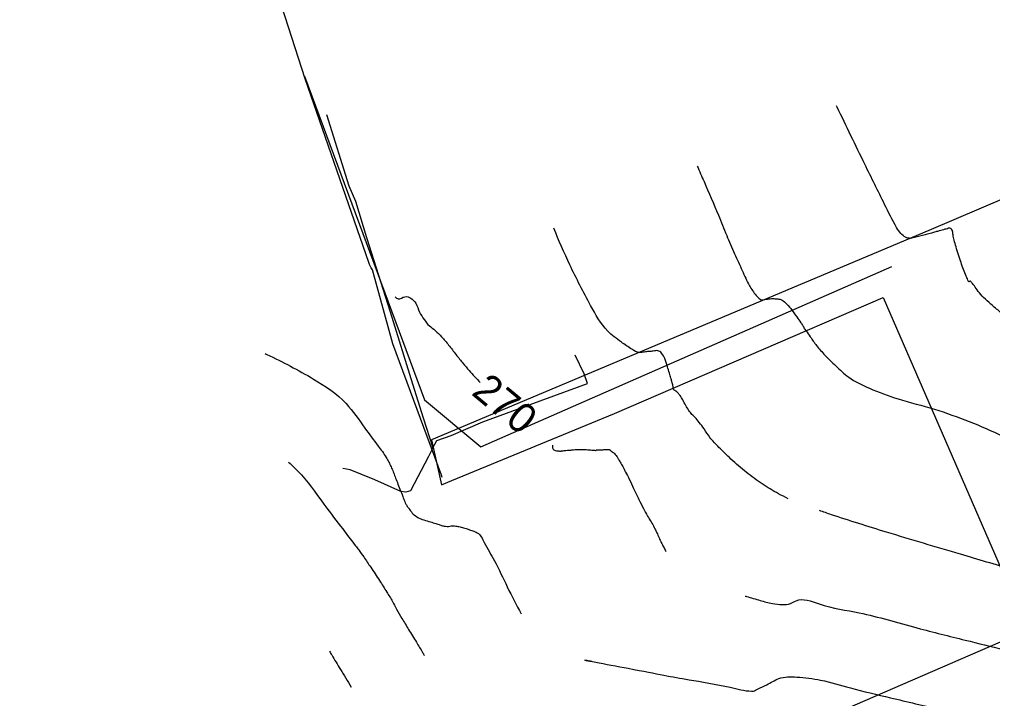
# Model space of a CAD drawing. Extents: x -478232 to -472707, y -1118753 to -1113967.
# Drawn here: x -475821.3 to -475689.5, y -1117014.2 to -1116922.3 of the extents above; entities that cross this region are included whole.
import ezdxf

# ---------------------------------------------------------------- set-up
doc = ezdxf.new("R2010")
doc.units = 0
for name, color, linetype in [('ObPÚ', 7, 'Continuous'), ('telekomunikační kabel_O2', 7, 'Continuous'), ('VAK_vodovod', 7, 'Continuous'), ('Vrstevnice_hlavni', 7, 'Continuous'), ('Vrstevnice_popis', 7, 'Continuous'), ('Vrstevnice_vedlejsi', 7, 'Continuous')]:
    doc.layers.add(name, color=color, linetype=linetype)

msp = doc.modelspace()

# ---------------------------------------------------------------- linework, layer by layer
at = {"layer": 'ObPÚ'}
msp.add_lwpolyline([(-475634.09, -1116923.52), (-475698.19, -1116950.87), (-475765.52, -1116979.2), (-475764.15, -1116985.27), (-475762.77, -1116984.68), (-475740.75, -1116975.6), (-475704.37, -1116959.91), (-475684.75, -1117004.96), (-475721.12, -1117020.7), (-475752.88, -1117034.21), (-475749.21, -1117050.03), (-475744.47, -1117062.49), (-475748.91, -1117064.2), (-475744.85, -1117076.56), (-475754.59, -1117081.64), (-475740.69, -1117110.42), (-475761.49, -1117122.43), (-475769.31, -1117126.94), (-475775.61, -1117130.12), (-475776.93, -1117131.38), (-475801.94, -1117143.82), (-475807.07, -1117146.05), (-475816.15, -1117150.33), (-475821.3, -1117143.22)], dxfattribs=at)
at = {"layer": 'telekomunikační kabel_O2'}
for points in [[(-475779.72, -1116935.16), (-475776.72, -1116944.8), (-475775.82, -1116946.89)], [(-475775.82, -1116946.89), (-475774.3, -1116951.81), (-475771.12, -1116961.84), (-475768.06, -1116971.62), (-475766.62, -1116976.22), (-475765.34, -1116980.29)], [(-475765.34, -1116980.29), (-475764.8, -1116979.28), (-475762.86, -1116978.62), (-475758.55, -1116976.73), (-475744.37, -1116971.54), (-475744.83, -1116970.26), (-475746.06, -1116967.73)], [(-475765.34, -1116980.29), (-475765.92, -1116981.46), (-475768.35, -1116986.07), (-475768.98, -1116986.28), (-475769.68, -1116986.19), (-475773.18, -1116984.59), (-475776.5, -1116983.23), (-475777.53, -1116983.05)]]:
    msp.add_lwpolyline(points, dxfattribs=at)
at = {"layer": 'VAK_vodovod'}
for points in [[(-475764.07, -1116984.29), (-475764.159, -1116983.95), (-475770.76, -1116966.2), (-475773.519, -1116956.18), (-475773.699, -1116955.909), (-475773.909, -1116955.44), (-475773.98, -1116955.18), (-475782.599, -1116930.34), (-475789.389, -1116909.29), (-475792.36, -1116901.129), (-475795.449, -1116892.25), (-475795.679, -1116891.569), (-475801.449, -1116877.079), (-475803.873, -1116870.356), (-475810.739, -1116851.899), (-475813.889, -1116838.01), (-475814.349, -1116835.61), (-475816.44, -1116816.799), (-475816.731, -1116810.878)], [(-475782.684, -1116929.977), (-475766.44, -1116973.781), (-475758.82, -1116980.133), (-475703.189, -1116955.74)]]:
    msp.add_lwpolyline(points, dxfattribs=at)
at = {"layer": 'Vrstevnice_hlavni'}
for points in [[(-475770.444, -1116959.812), (-475770.027, -1116960.112), (-475769.102, -1116959.807), (-475768.308, -1116960.004), (-475767.648, -1116960.702), (-475767.119, -1116961.902), (-475766.503, -1116962.916), (-475765.799, -1116963.743), (-475765.007, -1116964.385), (-475764.139, -1116965.254), (-475763.195, -1116966.349), (-475762.174, -1116967.671), (-475761.246, -1116968.823), (-475760.408, -1116969.806), (-475758.917, -1116971.433)], [(-475752.155, -1116974.761), (-475752.278, -1116974.524), (-475752.331, -1116974.447), (-475752.377, -1116974.41), (-475752.415, -1116974.415), (-475752.45, -1116974.42), (-475752.482, -1116974.426), (-475752.541, -1116974.439)], [(-475749.112, -1116979.911), (-475749.084, -1116980.363), (-475748.966, -1116980.529), (-475748.744, -1116980.634), (-475748.419, -1116980.68), (-475748.159, -1116980.701), (-475747.966, -1116980.699), (-475747.84, -1116980.673), (-475747.554, -1116980.64), (-475747.109, -1116980.599), (-475746.506, -1116980.551), (-475746.066, -1116980.515), (-475745.792, -1116980.49), (-475745.682, -1116980.477), (-475745.442, -1116980.476), (-475745.072, -1116980.485), (-475744.572, -1116980.507), (-475744.144, -1116980.533), (-475743.788, -1116980.563), (-475743.504, -1116980.598), (-475743.314, -1116980.614), (-475743.221, -1116980.611), (-475743.223, -1116980.59), (-475743.216, -1116980.574), (-475743.201, -1116980.564), (-475743.178, -1116980.559), (-475742.98, -1116980.549), (-475742.607, -1116980.532), (-475742.059, -1116980.51), (-475741.674, -1116980.502), (-475741.452, -1116980.509), (-475741.392, -1116980.531), (-475741.34, -1116980.559), (-475741.298, -1116980.593), (-475741.264, -1116980.634), (-475741.175, -1116980.708), (-475741.032, -1116980.815), (-475740.833, -1116980.954), (-475740.632, -1116981.157), (-475740.429, -1116981.424), (-475740.222, -1116981.754), (-475739.954, -1116982.217), (-475739.622, -1116982.813), (-475739.228, -1116983.543), (-475738.734, -1116984.524), (-475738.14, -1116985.756), (-475737.446, -1116987.241), (-475736.821, -1116988.49), (-475736.265, -1116989.503), (-475735.779, -1116990.281), (-475735.354, -1116991.032), (-475734.993, -1116991.754), (-475734.695, -1116992.449), (-475734.397, -1116993.087), (-475734.1, -1116993.67), (-475733.804, -1116994.197), (-475733.754, -1116994.287)], [(-475723.019, -1117000.326), (-475722.854, -1117000.379), (-475721.016, -1117000.925), (-475719.348, -1117001.335), (-475717.982, -1117001.478), (-475716.917, -1117001.356), (-475716.153, -1117000.967), (-475713.042, -1117001.384), (-475707.582, -1117002.608), (-475699.774, -1117004.638), (-475693.246, -1117006.296), (-475687.998, -1117007.584), (-475684.03, -1117008.499), (-475680.792, -1117009.282), (-475678.284, -1117009.933), (-475676.506, -1117010.452), (-475672.106, -1117010.892), (-475665.083, -1117011.253)]]:
    msp.add_spline(points, degree=3, dxfattribs=at)
at = {"layer": 'Vrstevnice_vedlejsi'}
for points in [[(-475589.216, -1117124.456), (-475591.425, -1117122.152), (-475592.659, -1117119.687), (-475592.919, -1117117.061), (-475592.203, -1117114.274), (-475589.888, -1117108.69), (-475585.974, -1117100.309), (-475580.459, -1117089.13), (-475576.812, -1117078.878), (-475575.031, -1117069.554), (-475575.117, -1117061.157), (-475574.636, -1117054.237), (-475573.59, -1117048.792), (-475571.977, -1117044.824), (-475570.898, -1117041.096), (-475570.353, -1117037.61), (-475570.342, -1117034.364), (-475569.433, -1117028.448), (-475567.626, -1117019.86), (-475564.922, -1117008.6), (-475567.235, -1116998.791), (-475574.567, -1116990.433), (-475586.916, -1116983.524), (-475597.186, -1116978.942), (-475605.377, -1116976.688), (-475611.489, -1116976.76), (-475618.025, -1116976.271), (-475624.984, -1116975.222), (-475632.368, -1116973.612), (-475641.296, -1116972.066), (-475651.771, -1116970.583), (-475663.792, -1116969.164), (-475672.17, -1116968.202), (-475676.905, -1116967.697), (-475677.998, -1116967.647), (-475679.435, -1116967.24), (-475681.215, -1116966.473), (-475683.339, -1116965.348), (-475684.96, -1116964.449), (-475686.077, -1116963.776), (-475686.69, -1116963.33), (-475687.51, -1116962.691), (-475688.536, -1116961.862), (-475689.768, -1116960.841), (-475690.758, -1116959.916), (-475691.505, -1116959.085), (-475692.008, -1116958.349), (-475692.376, -1116957.889), (-475692.608, -1116957.705), (-475692.704, -1116957.796), (-475692.881, -1116957.567), (-475693.138, -1116957.016), (-475693.475, -1116956.145), (-475693.813, -1116955.193), (-475694.151, -1116954.161), (-475694.489, -1116953.05), (-475694.736, -1116952.145), (-475694.892, -1116951.446), (-475694.956, -1116950.954), (-475695.105, -1116950.65), (-475695.339, -1116950.535), (-475695.658, -1116950.608), (-475696, -1116950.692), (-475696.364, -1116950.788), (-475696.75, -1116950.896), (-475697.237, -1116951.031), (-475697.824, -1116951.194), (-475698.511, -1116951.385), (-475699.213, -1116951.569), (-475699.928, -1116951.744), (-475700.656, -1116951.912), (-475701.333, -1116951.752), (-475701.956, -1116951.263), (-475702.527, -1116950.446), (-475704.154, -1116947.323), (-475706.837, -1116941.893), (-475710.575, -1116934.156), (-475710.663, -1116933.973)], [(-475729.527, -1116942.126), (-475728.611, -1116944.232), (-475726.669, -1116948.766), (-475725.544, -1116951.506), (-475724.466, -1116954.013), (-475723.434, -1116956.285), (-475722.449, -1116958.323), (-475721.548, -1116959.642), (-475720.729, -1116960.242), (-475719.994, -1116960.123), (-475719.328, -1116960.075), (-475718.731, -1116960.097), (-475718.204, -1116960.189), (-475717.583, -1116960.628), (-475716.868, -1116961.415), (-475716.061, -1116962.548), (-475715.508, -1116963.328), (-475715.21, -1116963.755), (-475715.167, -1116963.828), (-475715.132, -1116963.894), (-475715.104, -1116963.952), (-475715.085, -1116964.003), (-475714.792, -1116964.431), (-475714.224, -1116965.237), (-475713.382, -1116966.419), (-475712.234, -1116967.726), (-475710.782, -1116969.156), (-475709.024, -1116970.711), (-475706.212, -1116972.209), (-475702.344, -1116973.649), (-475697.421, -1116975.031), (-475692.698, -1116976.716), (-475688.176, -1116978.703), (-475683.853, -1116980.992), (-475678.496, -1116982.63), (-475672.102, -1116983.615), (-475664.674, -1116983.949), (-475657.807, -1116984.398), (-475651.502, -1116984.961), (-475645.759, -1116985.639), (-475640.754, -1116986.347), (-475636.487, -1116987.086), (-475632.96, -1116987.855), (-475627.187, -1116988.328), (-475619.17, -1116988.503), (-475608.909, -1116988.382), (-475599.585, -1116989.691), (-475591.198, -1116992.428), (-475583.75, -1116996.595), (-475579.328, -1117001.637), (-475577.932, -1117007.554), (-475579.563, -1117014.345), (-475580.658, -1117021.082), (-475581.217, -1117027.766), (-475581.24, -1117034.395), (-475582.353, -1117041.517), (-475584.557, -1117049.132), (-475587.852, -1117057.238), (-475590.037, -1117063.798), (-475591.112, -1117068.811)], [(-475717.205, -1116987.161), (-475718.526, -1116986.479), (-475720.741, -1116985.146), (-475722.885, -1116983.579), (-475724.958, -1116981.78), (-475726.601, -1116980.203), (-475727.814, -1116978.85), (-475728.597, -1116977.719), (-475729.263, -1116976.822), (-475729.811, -1116976.161), (-475730.242, -1116975.734), (-475730.666, -1116975.194), (-475731.082, -1116974.541), (-475731.491, -1116973.775), (-475731.855, -1116973.196), (-475732.174, -1116972.806), (-475732.448, -1116972.604), (-475732.637, -1116972.443), (-475732.741, -1116972.325), (-475732.761, -1116972.248), (-475732.78, -1116972.148), (-475732.799, -1116972.022), (-475732.818, -1116971.873), (-475732.873, -1116971.625), (-475732.966, -1116971.279), (-475733.095, -1116970.835), (-475733.299, -1116970.169), (-475733.575, -1116969.283), (-475733.925, -1116968.175), (-475734.359, -1116967.454), (-475734.877, -1116967.121), (-475735.478, -1116967.174), (-475736.089, -1116967.235), (-475736.708, -1116967.302), (-475737.336, -1116967.376), (-475738.368, -1116966.928), (-475739.805, -1116965.959), (-475741.646, -1116964.467), (-475743.969, -1116960.984), (-475746.775, -1116955.511), (-475748.963, -1116950.527)], [(-475788.03, -1116967.518), (-475787.795, -1116967.629), (-475781.498, -1116970.952), (-475777.078, -1116974.275), (-475774.537, -1116977.597), (-475772.727, -1116980.026), (-475771.647, -1116981.561), (-475771.297, -1116982.202), (-475770.979, -1116982.851), (-475770.692, -1116983.509), (-475770.437, -1116984.176), (-475770.136, -1116984.956), (-475769.79, -1116985.85), (-475769.398, -1116986.858), (-475769.136, -1116987.532), (-475769.004, -1116987.871), (-475769.002, -1116987.876), (-475769.001, -1116987.879), (-475769, -1116987.882), (-475768.999, -1116987.883), (-475768.999, -1116987.884), (-475768.998, -1116987.885), (-475768.852, -1116988.086), (-475768.561, -1116988.488), (-475768.125, -1116989.09), (-475767.529, -1116989.58), (-475766.772, -1116989.959), (-475765.856, -1116990.227), (-475765.092, -1116990.457), (-475764.483, -1116990.649), (-475764.027, -1116990.804), (-475763.601, -1116990.885), (-475763.205, -1116990.894), (-475762.84, -1116990.829), (-475762.377, -1116990.842), (-475761.816, -1116990.934), (-475761.157, -1116991.103), (-475760.523, -1116991.296), (-475759.914, -1116991.513), (-475759.331, -1116991.753), (-475758.359, -1116993.097), (-475756.997, -1116995.545), (-475755.247, -1116999.097), (-475753.369, -1117002.735)], [(-475784.856, -1116982.194), (-475783.127, -1116983.939), (-475779.673, -1116988.456), (-475777.228, -1116991.651), (-475775.793, -1116993.524), (-475775.368, -1116994.076), (-475774.686, -1116995.045), (-475773.746, -1116996.433), (-475772.548, -1116998.239), (-475771.564, -1116999.784), (-475770.793, -1117001.068), (-475770.234, -1117002.092), (-475769.508, -1117003.352), (-475768.615, -1117004.851), (-475767.555, -1117006.586), (-475766.714, -1117007.974), (-475766.472, -1117008.379)], [(-475648.003, -1117000.173), (-475655.316, -1116999.958), (-475662.118, -1116999.729), (-475668.41, -1116999.485), (-475674.19, -1116999.225), (-475678.133, -1116999.004), (-475680.239, -1116998.823), (-475680.506, -1116998.681), (-475681.023, -1116998.492), (-475681.789, -1116998.255), (-475682.805, -1116997.969), (-475686.83, -1116996.779), (-475693.865, -1116994.683), (-475703.91, -1116991.682), (-475711.368, -1116989.315), (-475712.997, -1116988.771)], [(-475779.319, -1117007.791), (-475779.013, -1117008.308), (-475777.842, -1117010.255), (-475776.381, -1117012.646)], [(-475743.816, -1117009.188), (-475744.435, -1117009.073), (-475738.882, -1117010.109), (-475730.644, -1117011.656), (-475725.08, -1117012.685), (-475722.191, -1117013.195), (-475721.975, -1117013.186), (-475721.285, -1117012.901), (-475720.12, -1117012.341), (-475718.481, -1117011.506), (-475716.047, -1117011.297), (-475712.82, -1117011.716), (-475708.798, -1117012.762), (-475703.378, -1117014.091), (-475696.56, -1117015.703), (-475688.344, -1117017.599), (-475681.639, -1117019.22), (-475676.446, -1117020.568), (-475672.765, -1117021.642), (-475668.29, -1117022.417), (-475663.022, -1117022.893), (-475656.96, -1117023.071), (-475651.811, -1117023.298), (-475647.576, -1117023.576), (-475644.255, -1117023.903), (-475641.565, -1117024.203), (-475639.507, -1117024.475)]]:
    msp.add_spline(points, degree=3, dxfattribs=at)

# ---------------------------------------------------------------- texts
at = {"layer": 'Vrstevnice_popis'}
msp.add_text(' 270 ', height=4, rotation=320.18645, dxfattribs=at).set_placement((-475761.384, -1116972.015))

doc.saveas('drawing.dxf')
